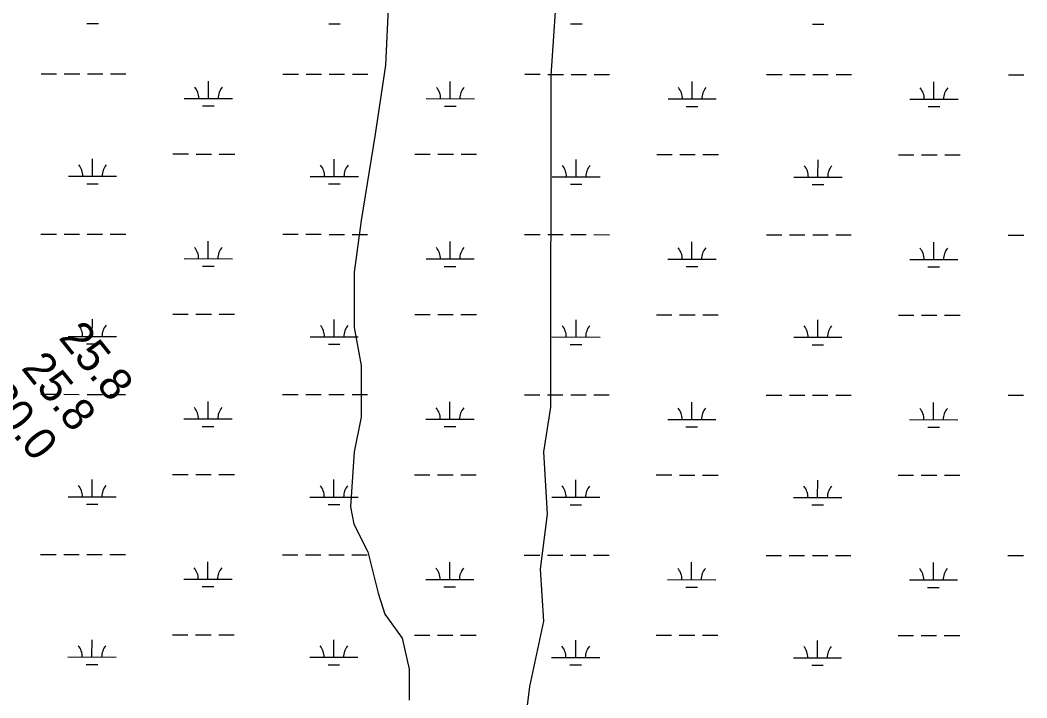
# Model space of a CAD drawing. Extents: x 3148686 to 3186545, y 916144 to 941516.
# Drawn here: x 3163116 to 3165206, y 937293 to 938700 of the extents above; entities that cross this region are included whole.
import ezdxf

# ---------------------------------------------------------------- set-up
doc = ezdxf.new("R2010")
doc.units = 0
for name, color, linetype in [('V-RIVR-RANG', 7, 'Continuous'), ('V-TOPO-SHOR', 7, 'Continuous'), ('V-WETL-SWMP', 7, 'Continuous')]:
    doc.layers.add(name, color=color, linetype=linetype)

msp = doc.modelspace()

# ---------------------------------------------------------------- linework, layer by layer
at = {"layer": 'V-TOPO-SHOR'}
for points in [[(3164152.6, 937144.4), (3164174.3, 937316.4), (3164203.1, 937452.5), (3164196, 937560), (3164210.5, 937674.7), (3164203.4, 937803.7), (3164217.9, 937896.9), (3164218.6, 938584.9), (3164247.7, 939014.9), (3164255, 939079.4), (3164269.3, 939108), (3164290.8, 939129.5), (3164326.7, 939158.1), (3164405.6, 939179.6), (3164520.2, 939179.4), (3164584.7, 939172.2), (3164713.7, 939157.7), (3164907.2, 939150.4), (3165086.4, 939143), (3165236.9, 939150)], [(3163884.1, 938814.5), (3163874.6, 938606.7), (3163853, 938463.4), (3163824.1, 938284.3), (3163809.6, 938176.8), (3163809.5, 938062.1), (3163823.8, 937983.3), (3163823.7, 937875.8), (3163809.3, 937804.1), (3163802, 937689.4), (3163809.1, 937653.6), (3163837.7, 937596.2), (3163859.1, 937510.2), (3163873.4, 937467.2), (3163909.2, 937417), (3163923.5, 937352.5), (3163923.4, 937288)]]:
    msp.add_lwpolyline(points, dxfattribs=at)
at = {"layer": 'V-WETL-SWMP'}
for p, q in [((3163254.7, 938693.2), (3163278.7, 938693.2)), ((3163756.6, 938692.7), (3163780.6, 938692.6)), ((3164258.5, 938692.1), (3164282.5, 938692.1)), ((3164760.5, 938691.6), (3164784.5, 938691.6)), ((3163159.8, 938588.7), (3163191.8, 938588.6)), ((3163207.8, 938588.6), (3163239.8, 938588.6)), ((3163255.8, 938588.6), (3163287.8, 938588.5)), ((3163303.8, 938588.5), (3163335.8, 938588.5)), ((3163661.7, 938588.1), (3163693.7, 938588.1)), ((3163709.7, 938588.1), (3163741.7, 938588)), ((3163757.7, 938588), (3163789.7, 938588)), ((3163805.7, 938588), (3163837.7, 938587.9)), ((3164163.6, 938587.6), (3164195.6, 938587.6)), ((3164211.6, 938587.5), (3164243.6, 938587.5)), ((3164259.6, 938587.5), (3164291.6, 938587.5)), ((3164307.6, 938587.4), (3164339.6, 938587.4)), ((3164665.5, 938587.1), (3164697.5, 938587)), ((3164713.5, 938587), (3164745.5, 938587)), ((3164761.5, 938587), (3164793.5, 938586.9)), ((3164809.5, 938586.9), (3164841.5, 938586.9)), ((3165167.4, 938586.5), (3165199.4, 938586.5)), ((3163507, 938537.5), (3163507.1, 938573.5)), ((3164008.9, 938537), (3164009, 938573)), ((3164510.9, 938536.5), (3164510.9, 938572.5)), ((3165012.8, 938536), (3165012.8, 938572)), ((3163457, 938537.6), (3163557, 938537.5)), ((3163495, 938522.1), (3163519, 938522.1)), ((3163958.9, 938537.1), (3164058.9, 938537)), ((3163996.9, 938521.6), (3164020.9, 938521.6)), ((3164460.9, 938536.5), (3164560.9, 938536.4)), ((3164498.8, 938521.1), (3164522.8, 938521)), ((3164962.8, 938536), (3165062.8, 938535.9)), ((3165000.7, 938520.5), (3165024.7, 938520.5)), ((3163433.5, 938422.2), (3163465.5, 938422.2)), ((3163481.5, 938422.1), (3163513.5, 938422.1)), ((3163529.5, 938422.1), (3163561.5, 938422.1)), ((3163935.4, 938421.7), (3163967.4, 938421.6)), ((3163983.4, 938421.6), (3164015.4, 938421.6)), ((3164031.4, 938421.6), (3164063.4, 938421.5)), ((3164437.3, 938421.1), (3164469.3, 938421.1)), ((3164485.3, 938421.1), (3164517.3, 938421.1)), ((3164533.3, 938421), (3164565.3, 938421)), ((3164939.2, 938420.6), (3164971.2, 938420.6)), ((3164987.2, 938420.6), (3165019.2, 938420.5)), ((3165035.2, 938420.5), (3165067.2, 938420.5)), ((3163266.4, 938375.9), (3163266.4, 938411.9)), ((3163768.3, 938375.4), (3163768.3, 938411.4)), ((3164270.2, 938374.9), (3164270.2, 938410.9)), ((3164772.1, 938374.4), (3164772.2, 938410.4)), ((3163216.4, 938376), (3163316.4, 938375.9)), ((3163718.3, 938375.5), (3163818.3, 938375.4)), ((3164220.2, 938374.9), (3164320.2, 938374.8)), ((3164722.1, 938374.4), (3164822.1, 938374.3)), ((3163254.4, 938360.5), (3163278.4, 938360.5)), ((3163756.3, 938360), (3163780.3, 938360)), ((3164258.2, 938359.5), (3164282.2, 938359.4)), ((3164760.1, 938358.9), (3164784.1, 938358.9)), ((3163159.4, 938256), (3163191.4, 938255.9)), ((3163207.4, 938255.9), (3163239.4, 938255.9)), ((3163255.4, 938255.9), (3163287.4, 938255.8)), ((3163303.4, 938255.8), (3163335.4, 938255.8)), ((3163661.3, 938255.5), (3163693.3, 938255.4)), ((3163709.3, 938255.4), (3163741.3, 938255.4)), ((3163757.3, 938255.3), (3163789.3, 938255.3)), ((3163805.3, 938255.3), (3163837.3, 938255.3)), ((3164163.2, 938254.9), (3164195.2, 938254.9)), ((3164211.2, 938254.9), (3164243.2, 938254.8)), ((3164259.2, 938254.8), (3164291.2, 938254.8)), ((3164307.2, 938254.8), (3164339.2, 938254.7)), ((3164665.1, 938254.4), (3164697.1, 938254.4)), ((3164713.1, 938254.3), (3164745.1, 938254.3)), ((3164761.1, 938254.3), (3164793.1, 938254.3)), ((3164809.1, 938254.2), (3164841.1, 938254.2)), ((3165167.1, 938253.9), (3165199.1, 938253.8)), ((3163506.7, 938204.9), (3163506.7, 938240.9)), ((3164008.6, 938204.3), (3164008.6, 938240.3)), ((3164510.5, 938203.8), (3164510.5, 938239.8)), ((3165012.4, 938203.3), (3165012.4, 938239.3)), ((3163456.7, 938204.9), (3163556.7, 938204.8)), ((3163494.7, 938189.5), (3163518.7, 938189.4)), ((3163958.6, 938204.4), (3164058.6, 938204.3)), ((3163996.6, 938188.9), (3164020.6, 938188.9)), ((3164460.5, 938203.9), (3164560.5, 938203.8)), ((3164498.5, 938188.4), (3164522.5, 938188.4)), ((3164962.4, 938203.3), (3165062.4, 938203.2)), ((3165000.4, 938187.9), (3165024.4, 938187.8)), ((3163266, 938043.3), (3163266.1, 938079.3)), ((3163433.2, 938089.5), (3163465.2, 938089.5)), ((3163481.2, 938089.5), (3163513.2, 938089.4)), ((3163529.2, 938089.4), (3163561.2, 938089.4)), ((3163935.1, 938089), (3163967.1, 938089)), ((3163983.1, 938088.9), (3164015.1, 938088.9)), ((3164031.1, 938088.9), (3164063.1, 938088.9)), ((3164437, 938088.5), (3164469, 938088.4)), ((3164485, 938088.4), (3164517, 938088.4)), ((3164533, 938088.4), (3164565, 938088.3)), ((3164938.9, 938087.9), (3164970.9, 938087.9)), ((3164986.9, 938087.9), (3165018.9, 938087.8)), ((3165034.9, 938087.8), (3165066.9, 938087.8)), ((3163768, 938042.7), (3163768, 938078.7)), ((3164269.9, 938042.2), (3164269.9, 938078.2)), ((3164771.8, 938041.7), (3164771.8, 938077.7)), ((3163216, 938043.3), (3163316, 938043.2)), ((3163718, 938042.8), (3163818, 938042.7)), ((3164219.9, 938042.3), (3164319.9, 938042.2)), ((3164721.8, 938041.7), (3164821.8, 938041.6)), ((3163254, 938027.8), (3163278, 938027.8)), ((3163755.9, 938027.3), (3163779.9, 938027.3)), ((3164257.8, 938026.8), (3164281.8, 938026.8)), ((3164759.8, 938026.3), (3164783.8, 938026.2)), ((3163159.1, 937923.3), (3163191.1, 937923.3)), ((3163207.1, 937923.3), (3163239.1, 937923.2)), ((3163255.1, 937923.2), (3163287.1, 937923.2)), ((3163303.1, 937923.2), (3163335.1, 937923.1)), ((3163661, 937922.8), (3163693, 937922.7)), ((3163709, 937922.7), (3163741, 937922.7)), ((3163757, 937922.7), (3163789, 937922.6)), ((3163805, 937922.6), (3163837, 937922.6)), ((3164162.9, 937922.2), (3164194.9, 937922.2)), ((3164210.9, 937922.2), (3164242.9, 937922.2)), ((3164258.9, 937922.1), (3164290.9, 937922.1)), ((3164306.9, 937922.1), (3164338.9, 937922.1)), ((3164664.8, 937921.7), (3164696.8, 937921.7)), ((3164712.8, 937921.7), (3164744.8, 937921.6)), ((3164760.8, 937921.6), (3164792.8, 937921.6)), ((3164808.8, 937921.6), (3164840.8, 937921.5)), ((3165166.7, 937921.2), (3165198.7, 937921.2)), ((3163506.3, 937872.2), (3163506.4, 937908.2)), ((3164008.2, 937871.7), (3164008.3, 937907.7)), ((3164510.2, 937871.1), (3164510.2, 937907.1)), ((3165012.1, 937870.6), (3165012.1, 937906.6)), ((3163456.3, 937872.2), (3163556.3, 937872.1)), ((3163958.2, 937871.7), (3164058.2, 937871.6)), ((3164460.2, 937871.2), (3164560.2, 937871.1)), ((3164962.1, 937870.7), (3165062.1, 937870.6)), ((3163494.3, 937856.8), (3163518.3, 937856.8)), ((3163996.2, 937856.2), (3164020.2, 937856.2)), ((3164498.1, 937855.7), (3164522.1, 937855.7)), ((3165000, 937855.2), (3165024, 937855.2)), ((3163265.7, 937710.6), (3163265.7, 937746.6)), ((3163432.8, 937756.8), (3163464.8, 937756.8)), ((3163480.8, 937756.8), (3163512.8, 937756.8)), ((3163528.8, 937756.7), (3163560.8, 937756.7)), ((3163767.6, 937710.1), (3163767.6, 937746.1)), ((3163934.7, 937756.3), (3163966.7, 937756.3)), ((3163982.7, 937756.3), (3164014.7, 937756.2)), ((3164030.7, 937756.2), (3164062.7, 937756.2)), ((3164269.5, 937709.5), (3164269.5, 937745.5)), ((3164436.6, 937755.8), (3164468.6, 937755.8)), ((3164484.6, 937755.7), (3164516.6, 937755.7)), ((3164532.6, 937755.7), (3164564.6, 937755.6)), ((3164771.4, 937709), (3164771.5, 937745)), ((3164938.5, 937755.3), (3164970.5, 937755.2)), ((3164986.5, 937755.2), (3165018.5, 937755.2)), ((3165034.5, 937755.2), (3165066.5, 937755.1)), ((3163215.7, 937710.6), (3163315.7, 937710.5)), ((3163717.6, 937710.1), (3163817.6, 937710)), ((3164219.5, 937709.6), (3164319.5, 937709.5)), ((3164721.4, 937709.1), (3164821.4, 937708.9)), ((3163253.7, 937695.2), (3163277.7, 937695.1)), ((3163755.6, 937694.6), (3163779.6, 937694.6)), ((3164257.5, 937694.1), (3164281.5, 937694.1)), ((3164759.4, 937693.6), (3164783.4, 937693.6)), ((3163158.7, 937590.6), (3163190.7, 937590.6)), ((3163206.7, 937590.6), (3163238.7, 937590.5)), ((3163254.7, 937590.5), (3163286.7, 937590.5)), ((3163302.7, 937590.5), (3163334.7, 937590.4)), ((3163660.6, 937590.1), (3163692.6, 937590.1)), ((3163708.6, 937590.1), (3163740.6, 937590)), ((3163756.6, 937590), (3163788.6, 937590)), ((3163804.6, 937589.9), (3163836.6, 937589.9)), ((3164162.5, 937589.6), (3164194.5, 937589.5)), ((3164210.5, 937589.5), (3164242.5, 937589.5)), ((3164258.5, 937589.5), (3164290.5, 937589.4)), ((3164306.5, 937589.4), (3164338.5, 937589.4)), ((3164664.4, 937589), (3164696.4, 937589)), ((3164712.4, 937589), (3164744.4, 937589)), ((3164760.4, 937588.9), (3164792.4, 937588.9)), ((3164808.4, 937588.9), (3164840.4, 937588.9)), ((3165166.4, 937588.5), (3165198.4, 937588.5)), ((3163506, 937539.5), (3163506, 937575.5)), ((3164007.9, 937539), (3164007.9, 937575)), ((3164509.8, 937538.5), (3164509.8, 937574.5)), ((3165011.7, 937537.9), (3165011.7, 937573.9)), ((3163456, 937539.6), (3163556, 937539.5)), ((3163957.9, 937539), (3164057.9, 937538.9)), ((3164459.8, 937538.5), (3164559.8, 937538.4)), ((3164961.7, 937538), (3165061.7, 937537.9)), ((3163494, 937524.1), (3163518, 937524.1)), ((3163995.9, 937523.6), (3164019.9, 937523.5)), ((3164497.8, 937523), (3164521.8, 937523)), ((3164999.7, 937522.5), (3165023.7, 937522.5)), ((3163265.3, 937377.9), (3163265.4, 937413.9)), ((3163432.5, 937424.2), (3163464.5, 937424.1)), ((3163480.5, 937424.1), (3163512.5, 937424.1)), ((3163528.5, 937424.1), (3163560.5, 937424)), ((3163767.3, 937377.4), (3163767.3, 937413.4)), ((3163934.4, 937423.6), (3163966.4, 937423.6)), ((3163982.4, 937423.6), (3164014.4, 937423.6)), ((3164030.4, 937423.5), (3164062.4, 937423.5)), ((3164269.2, 937376.9), (3164269.2, 937412.9)), ((3164436.3, 937423.1), (3164468.3, 937423.1)), ((3164484.3, 937423.1), (3164516.3, 937423)), ((3164532.3, 937423), (3164564.3, 937423)), ((3164771.1, 937376.3), (3164771.1, 937412.3)), ((3164938.2, 937422.6), (3164970.2, 937422.5)), ((3164986.2, 937422.5), (3165018.2, 937422.5)), ((3165034.2, 937422.5), (3165066.2, 937422.4)), ((3163215.3, 937378), (3163315.3, 937377.9)), ((3163717.3, 937377.4), (3163817.3, 937377.3)), ((3164219.2, 937376.9), (3164319.2, 937376.8)), ((3164721.1, 937376.4), (3164821.1, 937376.3)), ((3163253.3, 937362.5), (3163277.3, 937362.5)), ((3163755.2, 937362), (3163779.2, 937361.9)), ((3164257.1, 937361.4), (3164281.1, 937361.4)), ((3164759.1, 937360.9), (3164783.1, 937360.9))]:
    msp.add_line(p, q, dxfattribs=at)
for centre, start, end in [((3163451.8, 938538.1), 359.1678, 40.7115), ((3163562.3, 938538), 139.1678, 180.7115), ((3163953.7, 938537.6), 359.1678, 40.7115), ((3164064.2, 938537.4), 139.1678, 180.7115), ((3164455.6, 938537), 359.1678, 40.7115), ((3164566.1, 938536.9), 139.1678, 180.7115), ((3164957.5, 938536.5), 359.1678, 40.7115), ((3165068, 938536.4), 139.1678, 180.7115), ((3163211.2, 938376.5), 359.1678, 40.7115), ((3163321.6, 938376.4), 139.1678, 180.7115), ((3163713.1, 938375.9), 359.1678, 40.7115), ((3163823.5, 938375.8), 139.1678, 180.7115), ((3164215, 938375.4), 359.1678, 40.7115), ((3164325.5, 938375.3), 139.1678, 180.7115), ((3164716.9, 938374.9), 359.1678, 40.7115), ((3164827.4, 938374.8), 139.1678, 180.7115), ((3163451.4, 938205.4), 359.1678, 40.7115), ((3163561.9, 938205.3), 139.1678, 180.7115), ((3163953.4, 938204.9), 359.1678, 40.7115), ((3164063.8, 938204.8), 139.1678, 180.7115), ((3164455.3, 938204.3), 359.1678, 40.7115), ((3164565.7, 938204.2), 139.1678, 180.7115), ((3164957.2, 938203.8), 359.1678, 40.7115), ((3165067.7, 938203.7), 139.1678, 180.7115), ((3163210.8, 938043.8), 359.1678, 40.7115), ((3163321.3, 938043.7), 139.1678, 180.7115), ((3163712.7, 938043.3), 359.1678, 40.7115), ((3163823.2, 938043.2), 139.1678, 180.7115), ((3164214.6, 938042.7), 359.1678, 40.7115), ((3164325.1, 938042.6), 139.1678, 180.7115), ((3164716.5, 938042.2), 359.1678, 40.7115), ((3164827, 938042.1), 139.1678, 180.7115), ((3163451.1, 937872.7), 359.1678, 40.7115), ((3163561.6, 937872.6), 139.1678, 180.7115), ((3163953, 937872.2), 359.1678, 40.7115), ((3164063.5, 937872.1), 139.1678, 180.7115), ((3164454.9, 937871.7), 359.1678, 40.7115), ((3164565.4, 937871.6), 139.1678, 180.7115), ((3164956.8, 937871.1), 359.1678, 40.7115), ((3165067.3, 937871), 139.1678, 180.7115), ((3163210.5, 937711.1), 359.1678, 40.7115), ((3163320.9, 937711), 139.1678, 180.7115), ((3163712.4, 937710.6), 359.1678, 40.7115), ((3163822.8, 937710.5), 139.1678, 180.7115), ((3164214.3, 937710.1), 359.1678, 40.7115), ((3164324.8, 937709.9), 139.1678, 180.7115), ((3164716.2, 937709.5), 359.1678, 40.7115), ((3164826.7, 937709.4), 139.1678, 180.7115), ((3163450.7, 937540.1), 359.1678, 40.7115), ((3163561.2, 937539.9), 139.1678, 180.7115), ((3163952.7, 937539.5), 359.1678, 40.7115), ((3164063.1, 937539.4), 139.1678, 180.7115), ((3164454.6, 937539), 359.1678, 40.7115), ((3164565, 937538.9), 139.1678, 180.7115), ((3164956.5, 937538.5), 359.1678, 40.7115), ((3165067, 937538.4), 139.1678, 180.7115), ((3163210.1, 937378.4), 359.1678, 40.7115), ((3163320.6, 937378.3), 139.1678, 180.7115), ((3163712, 937377.9), 359.1678, 40.7115), ((3163822.5, 937377.8), 139.1678, 180.7115), ((3164213.9, 937377.4), 359.1678, 40.7115), ((3164324.4, 937377.3), 139.1678, 180.7115), ((3164715.8, 937376.9), 359.1678, 40.7115), ((3164826.3, 937376.7), 139.1678, 180.7115)]:
    msp.add_arc(centre, 35.2, start, end, dxfattribs=at)

# ---------------------------------------------------------------- texts
at = {"layer": 'V-RIVR-RANG'}
for s, p in [('25.8', (3163194.6, 938040.2)), ('25.8', (3163116.9, 937977.3)), ('30.0', (3163037.4, 937916.6))]:
    msp.add_text(s, height=67, rotation=308.8583, dxfattribs=at).set_placement(p)

doc.saveas('drawing.dxf')
